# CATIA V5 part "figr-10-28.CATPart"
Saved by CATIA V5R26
Part number: Part1
Bounding box of the stored display mesh (mm): x -60 to 70, y 0 to 100.393, z 0 to 0
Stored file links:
  D:\_Deepak\CATIA\CATIA V5-6R2016_Deepak\Resources\Part files\Partfiles\c10_catia_v5_6r2016_prt\figr-10-28.CATPart
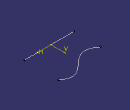
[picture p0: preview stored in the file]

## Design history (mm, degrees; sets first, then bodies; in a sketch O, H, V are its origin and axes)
Body1 (main body)
  Sketch1 on xy-plane, origin (0, 0, 0), H (1, 0, 0), V (0, 1, 0)
    line L1 (-60, 0) -> (70, 0)
    point P1 (-60, 0)
    coincidence: P1 H
    horizontal: L1 H
  Sketch2 on xy-plane, origin (0, 0, 0), H (1, 0, 0), V (0, 1, 0)
    spline S1 through (-60, 70) (-20, 60) (40, 100) (70, 90)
